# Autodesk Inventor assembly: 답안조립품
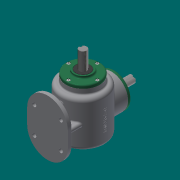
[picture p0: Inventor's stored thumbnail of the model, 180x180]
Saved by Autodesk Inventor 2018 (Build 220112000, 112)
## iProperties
Created: 2023-01
Part Number: 답안조립품
Material: 일반
Document SubType Name: Assembly
Designer: 강의실01
Author: 강의실01
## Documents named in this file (14)
- C:\Users\kimgi\Desktop\730106V1009\답안조립품.iam
- C:\Users\kimgi\Desktop\730106V1009\본체.ipt
- C:\Users\kimgi\Desktop\730106V1009\커버.ipt
- C:\Users\kimgi\Desktop\730106V1009\베어링 6203.ipt
- C:\Users\kimgi\Desktop\730106V1009\메인 축.ipt
- 메인 축.ipt
- C:\Users\kimgi\Desktop\730106V1009\오일실 17 32 8.ipt
- C:\Users\kimgi\Desktop\730106V1009\키 5x5.ipt
- C:\Users\kimgi\Desktop\730106V1009\메인 베벨기어.ipt
- C:\Users\kimgi\Desktop\730106V1009\서브 축.ipt
- 서브 축.ipt
- C:\Users\kimgi\Desktop\730106V1009\키 4x4.ipt
- C:\Users\kimgi\Desktop\730106V1009\서브 베벨기어.ipt
- C:\Users\kimgi\Desktop\730106V1009\M4.ipt
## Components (8 placed, 1 different names)
1. M4:1
2. M4:3
3. M4:4
4. M4:5
5. M4:2
6. M4:6
7. M4:7
8. M4:8
